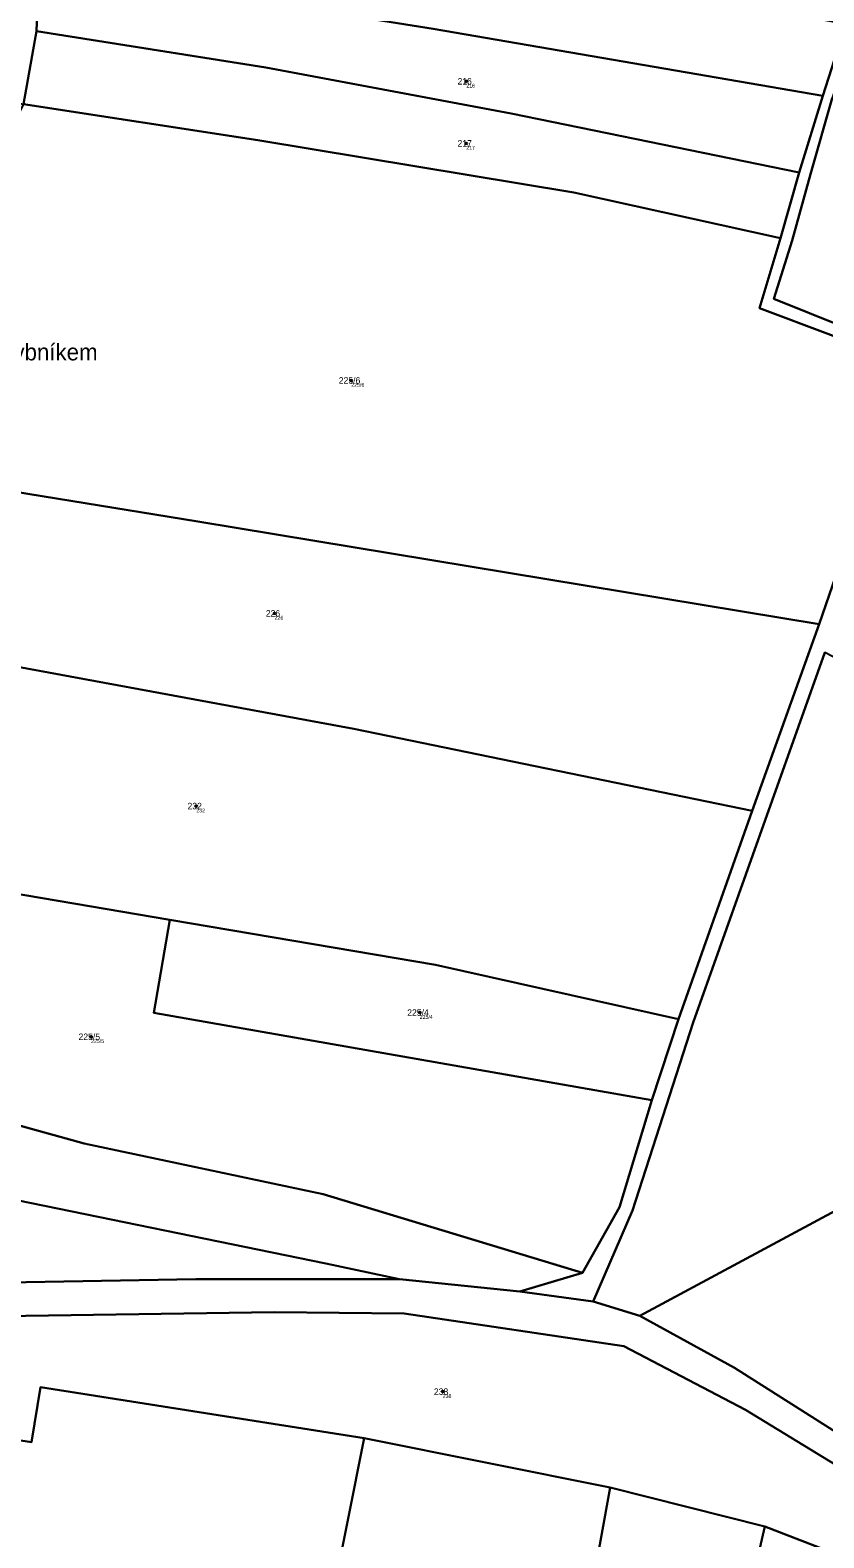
# Model space of a CAD drawing. Extents: x -700238 to -698499, y -1070626 to -1068006.
# Drawn here: x -699349.4 to -699139.8, y -1069308.9 to -1068910.8 of the extents above; entities that cross this region are included whole.
import ezdxf

# ---------------------------------------------------------------- set-up
doc = ezdxf.new("R2010")
doc.units = 0
for name, color, linetype in [('Definiční body', 7, 'Continuous'), ('Hranice parcel', 7, 'Continuous'), ('Parcelní čísla', 7, 'Continuous'), ('Polygon parcely', 7, 'Continuous'), ('Pop  PČ popisy', 7, 'Continuous')]:
    doc.layers.add(name, color=color, linetype=linetype)

msp = doc.modelspace()

# ---------------------------------------------------------------- linework, layer by layer
at = {"layer": 'Definiční body'}
for centre in [(-699234.23, -1068924.32994), (-699234.23, -1068940.71994), (-699264.62, -1069003.30994), (-699284.86, -1069064.80994), (-699305.55, -1069115.68994), (-699246.54, -1069170.20994), (-699333.36, -1069176.59994), (-699240.47, -1069270.29994)]:
    msp.add_circle(centre, 0.25, dxfattribs=at)
at = {"layer": 'Hranice parcel'}
for p, q in [((-699347.73, -1068911.07), (-699347.13, -1068893.81)), ((-699140.02, -1068928.19), (-699133.96, -1068909.29)), ((-699351.16, -1068930.36), (-699347.73, -1068911.07)), ((-699146.33, -1068948.42), (-699140.02, -1068928.19)), ((-699151.24, -1068965.73), (-699146.33, -1068948.42)), ((-699158.68, -1069116.94), (-699141, -1069067.64)), ((-699178.15, -1069171.96), (-699158.68, -1069116.94)), ((-699185.21, -1069193.37), (-699178.15, -1069171.96)), ((-699220.08, -1069243.89), (-699251.91, -1069240.63)), ((-699220.08, -1069243.89), (-699203.52, -1069238.89)), ((-699200.68, -1069246.54), (-699220.08, -1069243.89)), ((-699188.36, -1069250.3), (-699200.68, -1069246.54)), ((-699196.26, -1069295.61), (-699261.17, -1069282.59)), ((-699196.26, -1069295.61), (-699155.39, -1069305.92)), ((-699155.39, -1069305.92), (-699104.83, -1069325.44))]:
    msp.add_line(p, q, dxfattribs=at)
for points in [[(-699347.13, -1068893.81), (-699242.99, -1068910.5), (-699140.02, -1068928.19)], [(-699347.73, -1068911.07), (-699287.21, -1068920.71), (-699222.42, -1068932.84), (-699146.33, -1068948.42)], [(-699136.49, -1068925.34), (-699137.63, -1068928.8), (-699143.34, -1068948.89), (-699148.15, -1068966.39), (-699153.04, -1068981.73), (-699134.62, -1068989.13), (-699108.35, -1068996.32)], [(-699351.16, -1068930.36), (-699289.3, -1068939.86), (-699205.87, -1068953.7), (-699151.24, -1068965.73)], [(-699141, -1069067.64), (-699128.02, -1069029.95), (-699119.24, -1068998.27), (-699156.76, -1068984.27), (-699151.24, -1068965.73)], [(-699417.2, -1069022.3), (-699305.17, -1069040.57), (-699141, -1069067.64)], [(-699139.55, -1069075.18), (-699174.33, -1069172.85), (-699190.29, -1069222.45), (-699200.68, -1069246.54)], [(-699359.49, -1069077.72), (-699263.94, -1069095.27), (-699158.68, -1069116.94)], [(-699312.53, -1069145.7), (-699367.51, -1069136.37), (-699418.86, -1069126.42)], [(-699312.53, -1069145.7), (-699316.81, -1069170.25), (-699185.21, -1069193.37)], [(-699178.15, -1069171.96), (-699242.35, -1069157.62), (-699312.53, -1069145.7)], [(-699426.51, -1069178.06), (-699422.37, -1069179.4), (-699385.7, -1069190.83), (-699335.21, -1069204.79), (-699272.03, -1069218.19), (-699203.52, -1069238.89)], [(-699188.36, -1069250.3), (-699115.53, -1069211.13), (-699068.5, -1069188.78)], [(-699203.52, -1069238.89), (-699193.77, -1069221.63), (-699185.21, -1069193.37)], [(-699251.91, -1069240.63), (-699271.35, -1069236.43), (-699359.91, -1069218.33), (-699388.41, -1069213.11), (-699431.7, -1069205.56)], [(-699251.91, -1069240.63), (-699305.65, -1069240.58), (-699385.46, -1069242.05), (-699437.3, -1069240.27), (-699441.27, -1069241.07)], [(-699446.26, -1069252.77), (-699434.1, -1069251.54), (-699285, -1069249.35), (-699250.63, -1069249.65), (-699192.61, -1069258.25), (-699160.52, -1069275.07), (-699087.02, -1069319.88), (-699046.76, -1069345.16)], [(-699094.6, -1069307.55), (-699163.41, -1069264), (-699188.36, -1069250.3)], [(-699404.18, -1069271.48), (-699375.96, -1069279.46), (-699349.08, -1069283.63), (-699346.75, -1069269.14), (-699261.17, -1069282.59)], [(-699261.17, -1069282.59), (-699286.12, -1069407.64), (-699298.17, -1069477.84), (-699310.39, -1069530.09)], [(-699247.56, -1069569.1), (-699217.96, -1069415.59), (-699196.26, -1069295.61)], [(-699155.39, -1069305.92), (-699185.41, -1069435.95), (-699202.27, -1069502.69), (-699220.57, -1069583.09)]]:
    msp.add_lwpolyline(points, dxfattribs=at)
at = {"layer": 'Polygon parcely'}
for points in [[(-699340.34, -1068849.53), (-699346.21, -1068814.3), (-699359.15, -1068805.09), (-699354.24, -1068844.09), (-699360.66, -1068888.29), (-699372.07, -1068926.78), (-699351.16, -1068930.36), (-699347.73, -1068911.07), (-699347.13, -1068893.81), (-699345.65, -1068879.11), (-699343.95, -1068864.6)], [(-699133.96, -1068909.29), (-699178.12, -1068901.11), (-699223.74, -1068894.86), (-699345.65, -1068879.11), (-699347.13, -1068893.81), (-699242.99, -1068910.5), (-699140.02, -1068928.19)], [(-699222.42, -1068932.84), (-699146.33, -1068948.42), (-699140.02, -1068928.19), (-699242.99, -1068910.5), (-699347.13, -1068893.81), (-699347.73, -1068911.07), (-699287.21, -1068920.71)], [(-699289.3, -1068939.86), (-699205.87, -1068953.7), (-699151.24, -1068965.73), (-699146.33, -1068948.42), (-699222.42, -1068932.84), (-699287.21, -1068920.71), (-699347.73, -1068911.07), (-699351.16, -1068930.36)], [(-699153.04, -1068981.73), (-699134.62, -1068989.13), (-699108.35, -1068996.32), (-699059.55, -1069021.15), (-699011.24, -1069049.26), (-698990.02, -1069008.7), (-699136.49, -1068925.34), (-699137.63, -1068928.8), (-699143.34, -1068948.89), (-699148.15, -1068966.39)], [(-699417.2, -1069022.3), (-699305.17, -1069040.57), (-699141, -1069067.64), (-699128.02, -1069029.95), (-699119.24, -1068998.27), (-699156.76, -1068984.27), (-699151.24, -1068965.73), (-699205.87, -1068953.7), (-699289.3, -1068939.86), (-699351.16, -1068930.36), (-699361.06, -1068949.46), (-699389.97, -1068984.13), (-699400.27, -1068995.84), (-699406.14, -1069005.3)], [(-699359.49, -1069077.72), (-699263.94, -1069095.27), (-699158.68, -1069116.94), (-699141, -1069067.64), (-699305.17, -1069040.57), (-699417.2, -1069022.3), (-699437.26, -1069055.94), (-699358.41, -1069074.6)], [(-699158.68, -1069116.94), (-699263.94, -1069095.27), (-699359.49, -1069077.72), (-699440.07, -1069061.15), (-699454.75, -1069061.77), (-699460.96, -1069068.06), (-699462.85, -1069073.58), (-699476.22, -1069114.61), (-699471.05, -1069115.73), (-699418.86, -1069126.42), (-699367.51, -1069136.37), (-699312.53, -1069145.7), (-699242.35, -1069157.62), (-699178.15, -1069171.96)], [(-699200.68, -1069246.54), (-699188.36, -1069250.3), (-699115.53, -1069211.13), (-699068.5, -1069188.78), (-699033.5, -1069169.01), (-699005.85, -1069146.6), (-699005.49, -1069144.75), (-699139.55, -1069075.18), (-699174.33, -1069172.85), (-699190.29, -1069222.45)], [(-699185.21, -1069193.37), (-699316.81, -1069170.25), (-699312.53, -1069145.7), (-699367.51, -1069136.37), (-699418.86, -1069126.42), (-699426.51, -1069178.06), (-699422.37, -1069179.4), (-699385.7, -1069190.83), (-699335.21, -1069204.79), (-699272.03, -1069218.19), (-699203.52, -1069238.89), (-699193.77, -1069221.63)], [(-699178.15, -1069171.96), (-699242.35, -1069157.62), (-699312.53, -1069145.7), (-699316.81, -1069170.25), (-699185.21, -1069193.37)], [(-699203.52, -1069238.89), (-699272.03, -1069218.19), (-699335.21, -1069204.79), (-699385.7, -1069190.83), (-699422.37, -1069179.4), (-699426.51, -1069178.06), (-699483.97, -1069159.81), (-699465.44, -1069167.89), (-699429.12, -1069181.03), (-699427.03, -1069181.28), (-699431.7, -1069205.56), (-699388.41, -1069213.11), (-699359.91, -1069218.33), (-699271.35, -1069236.43), (-699251.91, -1069240.63), (-699220.08, -1069243.89)], [(-699094.6, -1069307.55), (-699068.5, -1069188.78), (-699115.53, -1069211.13), (-699188.36, -1069250.3), (-699163.41, -1069264)], [(-699359.91, -1069218.33), (-699388.41, -1069213.11), (-699431.7, -1069205.56), (-699434.39, -1069220.93), (-699441.27, -1069241.07), (-699437.3, -1069240.27), (-699385.46, -1069242.05), (-699305.65, -1069240.58), (-699251.91, -1069240.63), (-699271.35, -1069236.43)], [(-699375.96, -1069279.46), (-699349.08, -1069283.63), (-699346.75, -1069269.14), (-699261.17, -1069282.59), (-699196.26, -1069295.61), (-699155.39, -1069305.92), (-699104.83, -1069325.44), (-699046.76, -1069345.16), (-699087.02, -1069319.88), (-699160.52, -1069275.07), (-699192.61, -1069258.25), (-699250.63, -1069249.65), (-699285, -1069249.35), (-699434.1, -1069251.54), (-699446.26, -1069252.77), (-699404.18, -1069271.48)], [(-699450.57, -1069363.34), (-699496.32, -1069453.92), (-699455.92, -1069465.49), (-699428.14, -1069479.87), (-699405.11, -1069494.19), (-699389.85, -1069504.17), (-699341.47, -1069520.5), (-699310.39, -1069530.09), (-699298.17, -1069477.84), (-699286.12, -1069407.64), (-699261.17, -1069282.59), (-699346.75, -1069269.14), (-699349.08, -1069283.63), (-699375.96, -1069279.46), (-699404.18, -1069271.48)], [(-699261.17, -1069282.59), (-699286.12, -1069407.64), (-699298.17, -1069477.84), (-699310.39, -1069530.09), (-699281.05, -1069542.43), (-699247.56, -1069569.1), (-699217.96, -1069415.59), (-699196.26, -1069295.61)], [(-699247.56, -1069569.1), (-699220.57, -1069583.09), (-699202.27, -1069502.69), (-699185.41, -1069435.95), (-699155.39, -1069305.92), (-699196.26, -1069295.61), (-699217.96, -1069415.59)], [(-699202.27, -1069502.69), (-699220.57, -1069583.09), (-699182.85, -1069598.81), (-699154, -1069499.19), (-699122.92, -1069391.9), (-699104.83, -1069325.44), (-699155.39, -1069305.92), (-699185.41, -1069435.95)]]:
    msp.add_lwpolyline(points, close=True, dxfattribs=at)
for points in [[(-699133.96, -1068909.29), (-699140.02, -1068928.19), (-699146.33, -1068948.42), (-699151.24, -1068965.73), (-699156.76, -1068984.27), (-699119.24, -1068998.27)], [(-699134.62, -1068989.13), (-699153.04, -1068981.73), (-699148.15, -1068966.39), (-699143.34, -1068948.89), (-699137.63, -1068928.8)], [(-699128.02, -1069029.95), (-699141, -1069067.64), (-699158.68, -1069116.94), (-699178.15, -1069171.96), (-699185.21, -1069193.37), (-699193.77, -1069221.63), (-699203.52, -1069238.89), (-699220.08, -1069243.89), (-699200.68, -1069246.54), (-699190.29, -1069222.45), (-699174.33, -1069172.85), (-699139.55, -1069075.18)], [(-699094.6, -1069307.55), (-699163.41, -1069264), (-699188.36, -1069250.3), (-699200.68, -1069246.54), (-699220.08, -1069243.89), (-699251.91, -1069240.63), (-699305.65, -1069240.58), (-699385.46, -1069242.05), (-699437.3, -1069240.27), (-699441.27, -1069241.07), (-699444.8, -1069241.78), (-699450.98, -1069243.75), (-699496.25, -1069321.32)], [(-699492.9, -1069328.63), (-699446.26, -1069252.77), (-699434.1, -1069251.54), (-699285, -1069249.35), (-699250.63, -1069249.65), (-699192.61, -1069258.25), (-699160.52, -1069275.07), (-699087.02, -1069319.88)]]:
    msp.add_lwpolyline(points, dxfattribs=at)

# ---------------------------------------------------------------- texts
at = {"layer": 'Definiční body'}
for s, p in [('216', (-699234.23, -1068925.986)), ('217', (-699234.23, -1068942.376)), ('225/6', (-699264.62, -1069004.966)), ('226', (-699284.86, -1069066.466)), ('232', (-699305.55, -1069117.346)), ('225/4', (-699246.54, -1069171.866)), ('225/5', (-699333.36, -1069178.256)), ('238', (-699240.47, -1069271.956))]:
    msp.add_text(s, height=0.999996, dxfattribs=at).set_placement(p)
at = {"layer": 'Parcelní čísla'}
for s, p in [('216', (-699236.555, -1068925.18)), ('217', (-699236.555, -1068941.57)), ('225/6', (-699267.918, -1069004.16)), ('226', (-699287.185, -1069065.66)), ('232', (-699307.875, -1069116.54)), ('225/4', (-699249.838, -1069171.06)), ('225/5', (-699336.658, -1069177.45)), ('238', (-699242.795, -1069271.15))]:
    msp.add_text(s, height=1.699998, dxfattribs=at).set_placement(p)
at = {"layer": 'Pop  PČ popisy'}
msp.add_text('Za rybníkem', height=4.399998, dxfattribs=at).set_placement((-699364.319, -1068998.02))

doc.saveas('drawing.dxf')
